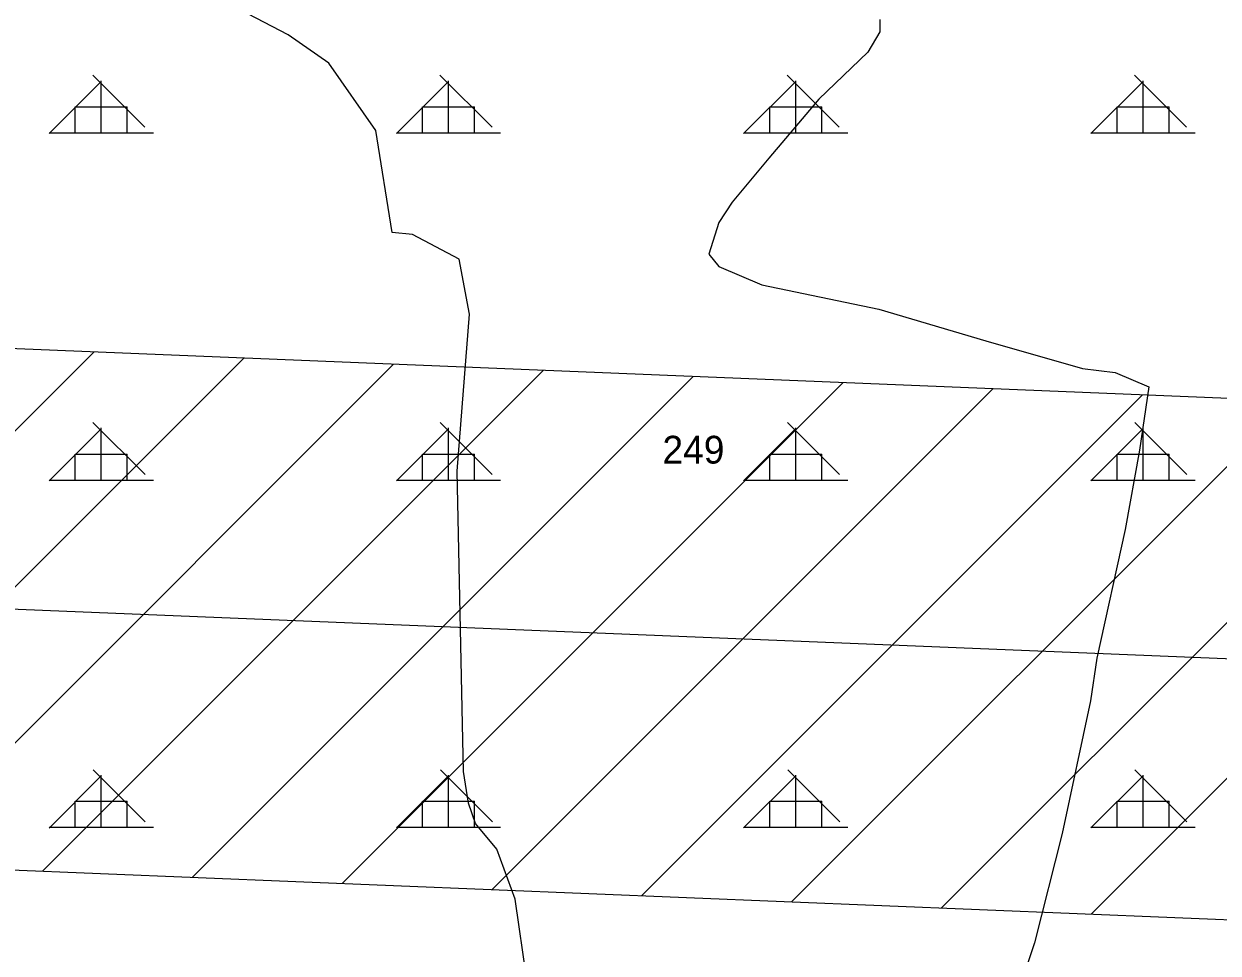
# Model space of a CAD drawing. Extents: x 410727 to 412947, y 4463506 to 4466382.
# Drawn here: x 411843.5 to 412015.4, y 4464905 to 4465038.8 of the extents above; entities that cross this region are included whole.
import ezdxf

# ---------------------------------------------------------------- set-up
doc = ezdxf.new("R2010")
doc.units = 0
for name, color, linetype in [('KDS_PARSEL_NO', 7, 'Continuous'), ('KDS_PL', 7, 'Continuous'), ('TA_ENH_HAT', 7, 'Continuous'), ('TA_ENH_TARAMA', 7, 'Continuous'), ('TR_ORMAN', 7, 'Continuous')]:
    doc.layers.add(name, color=color, linetype=linetype)

msp = doc.modelspace()

# ---------------------------------------------------------------- linework, layer by layer
at = {"layer": 'KDS_PL'}
for p, q in [((411881.55, 4465037.21), (411872.32, 4465042)), ((411966.73, 4465039.39), (411966.73, 4465037.63)), ((411887.41, 4465033.1), (411881.55, 4465037.21)), ((411966.73, 4465037.63), (411964.97, 4465034.69)), ((411964.97, 4465034.69), (411957.93, 4465027.94)), ((411894.16, 4465023.41), (411887.41, 4465033.1)), ((411957.93, 4465027.94), (411950.75, 4465019.42)), ((411896.5, 4465008.72), (411894.16, 4465023.41)), ((411950.75, 4465019.42), (411945.47, 4465013.1)), ((411945.47, 4465013.1), (411943.56, 4465010.16)), ((411899.43, 4465008.43), (411896.5, 4465008.72)), ((411943.56, 4465010.16), (411942.1, 4465005.61)), ((411906.17, 4465004.9), (411899.43, 4465008.43)), ((411942.1, 4465005.61), (411943.56, 4465003.85)), ((411907.64, 4464996.97), (411906.17, 4465004.9)), ((411943.56, 4465003.85), (411949.72, 4465001.2)), ((411949.72, 4465001.2), (411966.58, 4464997.68)), ((411905.88, 4464974.36), (411907.64, 4464996.97)), ((411966.58, 4464997.68), (411981.97, 4464993.13)), ((411981.97, 4464993.13), (411995.9, 4464989.16)), ((411995.9, 4464989.16), (412000.59, 4464988.57)), ((412000.59, 4464988.57), (412005.43, 4464986.52)), ((412005.43, 4464986.52), (412004.11, 4464977.41)), ((412004.11, 4464977.41), (412002.06, 4464965.95)), ((411906.76, 4464931.12), (411905.88, 4464974.36)), ((412002.06, 4464965.95), (411997.95, 4464947.45)), ((411997.95, 4464947.45), (411997.07, 4464941.28)), ((411997.07, 4464941.28), (411992.97, 4464922.18)), ((411907.49, 4464926.57), (411906.76, 4464931.12)), ((411908.52, 4464923.63), (411907.49, 4464926.57)), ((411911.59, 4464919.96), (411908.52, 4464923.63)), ((411992.97, 4464922.18), (411989.01, 4464906.46)), ((411914.23, 4464912.76), (411911.59, 4464919.96)), ((411916.14, 4464899.55), (411914.23, 4464912.76)), ((411989.01, 4464906.46), (411985.05, 4464894.86))]:
    msp.add_line(p, q, dxfattribs=at)
at = {"layer": 'TA_ENH_HAT'}
msp.add_lwpolyline([(412066.99, 4464945.27), (411603.01, 4464964.25), (411201.24, 4464983.22), (410781.64, 4465000.65)], dxfattribs=at)
at = {"layer": 'TA_ENH_TARAMA'}
for p, q in [((411781.47, 4464919.42), (411853.58, 4464991.53)), ((411781.47, 4464919.42), (411853.58, 4464991.53)), ((411803.03, 4464918.54), (411875.15, 4464990.65)), ((411803.03, 4464918.54), (411875.15, 4464990.65)), ((411824.6, 4464917.66), (411896.72, 4464989.77)), ((411824.6, 4464917.66), (411896.72, 4464989.77)), ((411846.17, 4464916.77), (411918.29, 4464988.89)), ((411846.17, 4464916.77), (411918.29, 4464988.89)), ((411867.74, 4464915.89), (411939.85, 4464988)), ((411867.74, 4464915.89), (411939.85, 4464988)), ((411889.31, 4464915.01), (411961.42, 4464987.12)), ((411889.31, 4464915.01), (411961.42, 4464987.12)), ((411910.88, 4464914.13), (411982.99, 4464986.24)), ((411910.88, 4464914.13), (411982.99, 4464986.24)), ((411932.45, 4464913.25), (412004.56, 4464985.36)), ((411932.45, 4464913.25), (412004.56, 4464985.36)), ((411954.02, 4464912.36), (412026.13, 4464984.48)), ((411954.02, 4464912.36), (412026.13, 4464984.48)), ((411975.58, 4464911.48), (412047.7, 4464983.59)), ((411975.58, 4464911.48), (412047.7, 4464983.59)), ((411997.15, 4464910.6), (412068.49, 4464981.94)), ((411997.15, 4464910.6), (412068.49, 4464981.94))]:
    msp.add_line(p, q, dxfattribs=at)
msp.add_lwpolyline([(410782.08, 4465038.16), (410781.19, 4464963.13), (411199.57, 4464945.75), (411601.36, 4464926.78), (412065.46, 4464907.81), (412068.53, 4464982.74), (411604.66, 4465001.71), (411202.9, 4465020.68), (410782.08, 4465038.16)], dxfattribs=at)
at = {"layer": 'TR_ORMAN'}
for p, q in [((411860.9, 4465023.92), (411853.4, 4465031.41)), ((411860.9, 4465023.92), (411853.4, 4465031.41)), ((411860.9, 4465023.92), (411853.4, 4465031.41)), ((411860.9, 4465023.92), (411853.4, 4465031.41)), ((411910.89, 4465023.92), (411903.39, 4465031.41)), ((411910.89, 4465023.92), (411903.39, 4465031.41)), ((411910.89, 4465023.92), (411903.39, 4465031.41)), ((411910.89, 4465023.92), (411903.39, 4465031.41)), ((411960.88, 4465023.92), (411953.38, 4465031.41)), ((411960.88, 4465023.92), (411953.38, 4465031.41)), ((411960.88, 4465023.92), (411953.38, 4465031.41)), ((411960.88, 4465023.92), (411953.38, 4465031.41)), ((412010.88, 4465023.92), (412003.38, 4465031.41)), ((412010.88, 4465023.92), (412003.38, 4465031.41)), ((412010.88, 4465023.92), (412003.38, 4465031.41)), ((412010.88, 4465023.92), (412003.38, 4465031.41)), ((411847.12, 4465022.97), (411854.61, 4465030.47)), ((411847.12, 4465022.97), (411854.61, 4465030.47)), ((411847.12, 4465022.97), (411854.61, 4465030.47)), ((411847.12, 4465022.97), (411854.61, 4465030.47)), ((411854.62, 4465023.09), (411854.62, 4465030.59)), ((411854.62, 4465023.09), (411854.62, 4465030.59)), ((411854.62, 4465023.09), (411854.62, 4465030.59)), ((411854.62, 4465023.09), (411854.62, 4465030.59)), ((411897.11, 4465022.97), (411904.61, 4465030.47)), ((411897.11, 4465022.97), (411904.61, 4465030.47)), ((411897.11, 4465022.97), (411904.61, 4465030.47)), ((411897.11, 4465022.97), (411904.61, 4465030.47)), ((411904.62, 4465023.09), (411904.62, 4465030.59)), ((411904.62, 4465023.09), (411904.62, 4465030.59)), ((411904.62, 4465023.09), (411904.62, 4465030.59)), ((411904.62, 4465023.09), (411904.62, 4465030.59)), ((411947.11, 4465022.98), (411954.61, 4465030.48)), ((411947.11, 4465022.98), (411954.61, 4465030.48)), ((411947.11, 4465022.98), (411954.61, 4465030.48)), ((411947.11, 4465022.98), (411954.61, 4465030.48)), ((411954.62, 4465023.09), (411954.62, 4465030.59)), ((411954.62, 4465023.09), (411954.62, 4465030.59)), ((411954.62, 4465023.09), (411954.62, 4465030.59)), ((411954.62, 4465023.09), (411954.62, 4465030.59)), ((411997.11, 4465022.99), (412004.61, 4465030.49)), ((411997.11, 4465022.99), (412004.61, 4465030.49)), ((411997.11, 4465022.99), (412004.61, 4465030.49)), ((411997.11, 4465022.99), (412004.61, 4465030.49)), ((412004.62, 4465023.09), (412004.62, 4465030.59)), ((412004.62, 4465023.09), (412004.62, 4465030.59)), ((412004.62, 4465023.09), (412004.62, 4465030.59)), ((412004.62, 4465023.09), (412004.62, 4465030.59)), ((411850.87, 4465023.09), (411850.87, 4465026.84)), ((411850.87, 4465026.84), (411858.37, 4465026.84)), ((411850.87, 4465023.09), (411850.87, 4465026.84)), ((411850.87, 4465026.84), (411858.37, 4465026.84)), ((411850.87, 4465023.09), (411850.87, 4465026.84)), ((411850.87, 4465026.84), (411858.37, 4465026.84)), ((411850.87, 4465023.09), (411850.87, 4465026.84)), ((411850.87, 4465026.84), (411858.37, 4465026.84)), ((411858.37, 4465023.09), (411858.37, 4465026.84)), ((411858.37, 4465023.09), (411858.37, 4465026.84)), ((411858.37, 4465023.09), (411858.37, 4465026.84)), ((411858.37, 4465023.09), (411858.37, 4465026.84)), ((411900.87, 4465023.09), (411900.87, 4465026.84)), ((411900.87, 4465026.84), (411908.37, 4465026.84)), ((411900.87, 4465023.09), (411900.87, 4465026.84)), ((411900.87, 4465026.84), (411908.37, 4465026.84)), ((411900.87, 4465023.09), (411900.87, 4465026.84)), ((411900.87, 4465026.84), (411908.37, 4465026.84)), ((411900.87, 4465023.09), (411900.87, 4465026.84)), ((411900.87, 4465026.84), (411908.37, 4465026.84)), ((411908.37, 4465023.09), (411908.37, 4465026.84)), ((411908.37, 4465023.09), (411908.37, 4465026.84)), ((411908.37, 4465023.09), (411908.37, 4465026.84)), ((411908.37, 4465023.09), (411908.37, 4465026.84)), ((411950.87, 4465023.09), (411950.87, 4465026.84)), ((411950.87, 4465026.84), (411958.37, 4465026.84)), ((411950.87, 4465023.09), (411950.87, 4465026.84)), ((411950.87, 4465026.84), (411958.37, 4465026.84)), ((411950.87, 4465023.09), (411950.87, 4465026.84)), ((411950.87, 4465026.84), (411958.37, 4465026.84)), ((411950.87, 4465023.09), (411950.87, 4465026.84)), ((411950.87, 4465026.84), (411958.37, 4465026.84)), ((411958.37, 4465023.09), (411958.37, 4465026.84)), ((411958.37, 4465023.09), (411958.37, 4465026.84)), ((411958.37, 4465023.09), (411958.37, 4465026.84)), ((411958.37, 4465023.09), (411958.37, 4465026.84)), ((412000.87, 4465023.09), (412000.87, 4465026.84)), ((412000.87, 4465026.84), (412008.37, 4465026.84)), ((412000.87, 4465023.09), (412000.87, 4465026.84)), ((412000.87, 4465026.84), (412008.37, 4465026.84)), ((412000.87, 4465023.09), (412000.87, 4465026.84)), ((412000.87, 4465026.84), (412008.37, 4465026.84)), ((412000.87, 4465023.09), (412000.87, 4465026.84)), ((412000.87, 4465026.84), (412008.37, 4465026.84)), ((412008.37, 4465023.09), (412008.37, 4465026.84)), ((412008.37, 4465023.09), (412008.37, 4465026.84)), ((412008.37, 4465023.09), (412008.37, 4465026.84)), ((412008.37, 4465023.09), (412008.37, 4465026.84)), ((411847.12, 4465023.09), (411862.12, 4465023.09)), ((411847.12, 4465023.09), (411862.12, 4465023.09)), ((411847.12, 4465023.09), (411862.12, 4465023.09)), ((411847.12, 4465023.09), (411862.12, 4465023.09)), ((411897.12, 4465023.09), (411912.12, 4465023.09)), ((411897.12, 4465023.09), (411912.12, 4465023.09)), ((411897.12, 4465023.09), (411912.12, 4465023.09)), ((411897.12, 4465023.09), (411912.12, 4465023.09)), ((411947.12, 4465023.09), (411962.12, 4465023.09)), ((411947.12, 4465023.09), (411962.12, 4465023.09)), ((411947.12, 4465023.09), (411962.12, 4465023.09)), ((411947.12, 4465023.09), (411962.12, 4465023.09)), ((411997.12, 4465023.09), (412012.12, 4465023.09)), ((411997.12, 4465023.09), (412012.12, 4465023.09)), ((411997.12, 4465023.09), (412012.12, 4465023.09)), ((411997.12, 4465023.09), (412012.12, 4465023.09)), ((411860.93, 4464973.89), (411853.43, 4464981.39)), ((411860.93, 4464973.89), (411853.43, 4464981.39)), ((411860.93, 4464973.89), (411853.43, 4464981.39)), ((411860.93, 4464973.89), (411853.43, 4464981.39)), ((411910.92, 4464973.89), (411903.42, 4464981.39)), ((411910.92, 4464973.89), (411903.42, 4464981.39)), ((411910.92, 4464973.89), (411903.42, 4464981.39)), ((411910.92, 4464973.89), (411903.42, 4464981.39)), ((411960.92, 4464973.89), (411953.42, 4464981.39)), ((411960.92, 4464973.89), (411953.42, 4464981.39)), ((411960.92, 4464973.89), (411953.42, 4464981.39)), ((411960.92, 4464973.89), (411953.42, 4464981.39)), ((412010.91, 4464973.89), (412003.41, 4464981.39)), ((412010.91, 4464973.89), (412003.41, 4464981.39)), ((412010.91, 4464973.89), (412003.41, 4464981.39)), ((412010.91, 4464973.89), (412003.41, 4464981.39)), ((411847.12, 4464972.98), (411854.61, 4464980.47)), ((411847.12, 4464972.98), (411854.61, 4464980.47)), ((411847.12, 4464972.98), (411854.61, 4464980.47)), ((411847.12, 4464972.98), (411854.61, 4464980.47)), ((411854.62, 4464973.09), (411854.62, 4464980.59)), ((411854.62, 4464973.09), (411854.62, 4464980.59)), ((411854.62, 4464973.09), (411854.62, 4464980.59)), ((411854.62, 4464973.09), (411854.62, 4464980.59)), ((411897.11, 4464972.98), (411904.61, 4464980.48)), ((411897.11, 4464972.98), (411904.61, 4464980.48)), ((411897.11, 4464972.98), (411904.61, 4464980.48)), ((411897.11, 4464972.98), (411904.61, 4464980.48)), ((411904.62, 4464973.09), (411904.62, 4464980.59)), ((411904.62, 4464973.09), (411904.62, 4464980.59)), ((411904.62, 4464973.09), (411904.62, 4464980.59)), ((411904.62, 4464973.09), (411904.62, 4464980.59)), ((411947.11, 4464972.99), (411954.61, 4464980.49)), ((411947.11, 4464972.99), (411954.61, 4464980.49)), ((411947.11, 4464972.99), (411954.61, 4464980.49)), ((411947.11, 4464972.99), (411954.61, 4464980.49)), ((411954.62, 4464973.09), (411954.62, 4464980.59)), ((411954.62, 4464973.09), (411954.62, 4464980.59)), ((411954.62, 4464973.09), (411954.62, 4464980.59)), ((411954.62, 4464973.09), (411954.62, 4464980.59)), ((411997.11, 4464973), (412004.61, 4464980.5)), ((411997.11, 4464973), (412004.61, 4464980.5)), ((411997.11, 4464973), (412004.61, 4464980.5)), ((411997.11, 4464973), (412004.61, 4464980.5)), ((412004.62, 4464973.09), (412004.62, 4464980.59)), ((412004.62, 4464973.09), (412004.62, 4464980.59)), ((412004.62, 4464973.09), (412004.62, 4464980.59)), ((412004.62, 4464973.09), (412004.62, 4464980.59)), ((411850.87, 4464973.09), (411850.87, 4464976.84)), ((411850.87, 4464976.84), (411858.37, 4464976.84)), ((411850.87, 4464973.09), (411850.87, 4464976.84)), ((411850.87, 4464976.84), (411858.37, 4464976.84)), ((411850.87, 4464973.09), (411850.87, 4464976.84)), ((411850.87, 4464976.84), (411858.37, 4464976.84)), ((411850.87, 4464973.09), (411850.87, 4464976.84)), ((411850.87, 4464976.84), (411858.37, 4464976.84)), ((411858.37, 4464973.09), (411858.37, 4464976.84)), ((411858.37, 4464973.09), (411858.37, 4464976.84)), ((411858.37, 4464973.09), (411858.37, 4464976.84)), ((411858.37, 4464973.09), (411858.37, 4464976.84)), ((411900.87, 4464973.09), (411900.87, 4464976.84)), ((411900.87, 4464976.84), (411908.37, 4464976.84)), ((411900.87, 4464973.09), (411900.87, 4464976.84)), ((411900.87, 4464976.84), (411908.37, 4464976.84)), ((411900.87, 4464973.09), (411900.87, 4464976.84)), ((411900.87, 4464976.84), (411908.37, 4464976.84)), ((411900.87, 4464973.09), (411900.87, 4464976.84)), ((411900.87, 4464976.84), (411908.37, 4464976.84)), ((411908.37, 4464973.09), (411908.37, 4464976.84)), ((411908.37, 4464973.09), (411908.37, 4464976.84)), ((411908.37, 4464973.09), (411908.37, 4464976.84)), ((411908.37, 4464973.09), (411908.37, 4464976.84)), ((411950.87, 4464973.09), (411950.87, 4464976.84)), ((411950.87, 4464976.84), (411958.37, 4464976.84)), ((411950.87, 4464973.09), (411950.87, 4464976.84)), ((411950.87, 4464976.84), (411958.37, 4464976.84)), ((411950.87, 4464973.09), (411950.87, 4464976.84)), ((411950.87, 4464976.84), (411958.37, 4464976.84)), ((411950.87, 4464973.09), (411950.87, 4464976.84)), ((411950.87, 4464976.84), (411958.37, 4464976.84)), ((411958.37, 4464973.09), (411958.37, 4464976.84)), ((411958.37, 4464973.09), (411958.37, 4464976.84)), ((411958.37, 4464973.09), (411958.37, 4464976.84)), ((411958.37, 4464973.09), (411958.37, 4464976.84)), ((412000.87, 4464973.09), (412000.87, 4464976.84)), ((412000.87, 4464976.84), (412008.37, 4464976.84)), ((412000.87, 4464973.09), (412000.87, 4464976.84)), ((412000.87, 4464976.84), (412008.37, 4464976.84)), ((412000.87, 4464973.09), (412000.87, 4464976.84)), ((412000.87, 4464976.84), (412008.37, 4464976.84)), ((412000.87, 4464973.09), (412000.87, 4464976.84)), ((412000.87, 4464976.84), (412008.37, 4464976.84)), ((412008.37, 4464973.09), (412008.37, 4464976.84)), ((412008.37, 4464973.09), (412008.37, 4464976.84)), ((412008.37, 4464973.09), (412008.37, 4464976.84)), ((412008.37, 4464973.09), (412008.37, 4464976.84)), ((411847.12, 4464973.09), (411862.12, 4464973.09)), ((411847.12, 4464973.09), (411862.12, 4464973.09)), ((411847.12, 4464973.09), (411862.12, 4464973.09)), ((411847.12, 4464973.09), (411862.12, 4464973.09)), ((411897.12, 4464973.09), (411912.12, 4464973.09)), ((411897.12, 4464973.09), (411912.12, 4464973.09)), ((411897.12, 4464973.09), (411912.12, 4464973.09)), ((411897.12, 4464973.09), (411912.12, 4464973.09)), ((411947.12, 4464973.09), (411962.12, 4464973.09)), ((411947.12, 4464973.09), (411962.12, 4464973.09)), ((411947.12, 4464973.09), (411962.12, 4464973.09)), ((411947.12, 4464973.09), (411962.12, 4464973.09)), ((411997.12, 4464973.09), (412012.12, 4464973.09)), ((411997.12, 4464973.09), (412012.12, 4464973.09)), ((411997.12, 4464973.09), (412012.12, 4464973.09)), ((411997.12, 4464973.09), (412012.12, 4464973.09)), ((411860.96, 4464923.87), (411853.46, 4464931.37)), ((411860.96, 4464923.87), (411853.46, 4464931.37)), ((411860.96, 4464923.87), (411853.46, 4464931.37)), ((411860.96, 4464923.87), (411853.46, 4464931.37)), ((411910.95, 4464923.87), (411903.46, 4464931.37)), ((411910.95, 4464923.87), (411903.46, 4464931.37)), ((411910.95, 4464923.87), (411903.46, 4464931.37)), ((411910.95, 4464923.87), (411903.46, 4464931.37)), ((411960.95, 4464923.87), (411953.45, 4464931.37)), ((411960.95, 4464923.87), (411953.45, 4464931.37)), ((411960.95, 4464923.87), (411953.45, 4464931.37)), ((411960.95, 4464923.87), (411953.45, 4464931.37)), ((412010.94, 4464923.87), (412003.44, 4464931.37)), ((412010.94, 4464923.87), (412003.44, 4464931.37)), ((412010.94, 4464923.87), (412003.44, 4464931.37)), ((412010.94, 4464923.87), (412003.44, 4464931.37)), ((411847.12, 4464922.98), (411854.61, 4464930.48)), ((411847.12, 4464922.98), (411854.61, 4464930.48)), ((411847.12, 4464922.98), (411854.61, 4464930.48)), ((411847.12, 4464922.98), (411854.61, 4464930.48)), ((411854.62, 4464923.09), (411854.62, 4464930.59)), ((411854.62, 4464923.09), (411854.62, 4464930.59)), ((411854.62, 4464923.09), (411854.62, 4464930.59)), ((411854.62, 4464923.09), (411854.62, 4464930.59)), ((411897.11, 4464922.99), (411904.61, 4464930.49)), ((411897.11, 4464922.99), (411904.61, 4464930.49)), ((411897.11, 4464922.99), (411904.61, 4464930.49)), ((411897.11, 4464922.99), (411904.61, 4464930.49)), ((411904.62, 4464923.09), (411904.62, 4464930.59)), ((411904.62, 4464923.09), (411904.62, 4464930.59)), ((411904.62, 4464923.09), (411904.62, 4464930.59)), ((411904.62, 4464923.09), (411904.62, 4464930.59)), ((411947.11, 4464923), (411954.61, 4464930.5)), ((411947.11, 4464923), (411954.61, 4464930.5)), ((411947.11, 4464923), (411954.61, 4464930.5)), ((411947.11, 4464923), (411954.61, 4464930.5)), ((411954.62, 4464923.09), (411954.62, 4464930.59)), ((411954.62, 4464923.09), (411954.62, 4464930.59)), ((411954.62, 4464923.09), (411954.62, 4464930.59)), ((411954.62, 4464923.09), (411954.62, 4464930.59)), ((411997.11, 4464923), (412004.61, 4464930.5)), ((411997.11, 4464923), (412004.61, 4464930.5)), ((411997.11, 4464923), (412004.61, 4464930.5)), ((411997.11, 4464923), (412004.61, 4464930.5)), ((412004.62, 4464923.09), (412004.62, 4464930.59)), ((412004.62, 4464923.09), (412004.62, 4464930.59)), ((412004.62, 4464923.09), (412004.62, 4464930.59)), ((412004.62, 4464923.09), (412004.62, 4464930.59)), ((411850.87, 4464923.09), (411850.87, 4464926.84)), ((411850.87, 4464926.84), (411858.37, 4464926.84)), ((411850.87, 4464923.09), (411850.87, 4464926.84)), ((411850.87, 4464926.84), (411858.37, 4464926.84)), ((411850.87, 4464923.09), (411850.87, 4464926.84)), ((411850.87, 4464926.84), (411858.37, 4464926.84)), ((411850.87, 4464923.09), (411850.87, 4464926.84)), ((411850.87, 4464926.84), (411858.37, 4464926.84)), ((411858.37, 4464923.09), (411858.37, 4464926.84)), ((411858.37, 4464923.09), (411858.37, 4464926.84)), ((411858.37, 4464923.09), (411858.37, 4464926.84)), ((411858.37, 4464923.09), (411858.37, 4464926.84)), ((411900.87, 4464923.09), (411900.87, 4464926.84)), ((411900.87, 4464926.84), (411908.37, 4464926.84)), ((411900.87, 4464923.09), (411900.87, 4464926.84)), ((411900.87, 4464926.84), (411908.37, 4464926.84)), ((411900.87, 4464923.09), (411900.87, 4464926.84)), ((411900.87, 4464926.84), (411908.37, 4464926.84)), ((411900.87, 4464923.09), (411900.87, 4464926.84)), ((411900.87, 4464926.84), (411908.37, 4464926.84)), ((411908.37, 4464923.09), (411908.37, 4464926.84)), ((411908.37, 4464923.09), (411908.37, 4464926.84)), ((411908.37, 4464923.09), (411908.37, 4464926.84)), ((411908.37, 4464923.09), (411908.37, 4464926.84)), ((411950.87, 4464923.09), (411950.87, 4464926.84)), ((411950.87, 4464926.84), (411958.37, 4464926.84)), ((411950.87, 4464923.09), (411950.87, 4464926.84)), ((411950.87, 4464926.84), (411958.37, 4464926.84)), ((411950.87, 4464923.09), (411950.87, 4464926.84)), ((411950.87, 4464926.84), (411958.37, 4464926.84)), ((411950.87, 4464923.09), (411950.87, 4464926.84)), ((411950.87, 4464926.84), (411958.37, 4464926.84)), ((411958.37, 4464923.09), (411958.37, 4464926.84)), ((411958.37, 4464923.09), (411958.37, 4464926.84)), ((411958.37, 4464923.09), (411958.37, 4464926.84)), ((411958.37, 4464923.09), (411958.37, 4464926.84)), ((412000.87, 4464923.09), (412000.87, 4464926.84)), ((412000.87, 4464926.84), (412008.37, 4464926.84)), ((412000.87, 4464923.09), (412000.87, 4464926.84)), ((412000.87, 4464926.84), (412008.37, 4464926.84)), ((412000.87, 4464923.09), (412000.87, 4464926.84)), ((412000.87, 4464926.84), (412008.37, 4464926.84)), ((412000.87, 4464923.09), (412000.87, 4464926.84)), ((412000.87, 4464926.84), (412008.37, 4464926.84)), ((412008.37, 4464923.09), (412008.37, 4464926.84)), ((412008.37, 4464923.09), (412008.37, 4464926.84)), ((412008.37, 4464923.09), (412008.37, 4464926.84)), ((412008.37, 4464923.09), (412008.37, 4464926.84)), ((411847.12, 4464923.09), (411862.12, 4464923.09)), ((411847.12, 4464923.09), (411862.12, 4464923.09)), ((411847.12, 4464923.09), (411862.12, 4464923.09)), ((411847.12, 4464923.09), (411862.12, 4464923.09)), ((411897.12, 4464923.09), (411912.12, 4464923.09)), ((411897.12, 4464923.09), (411912.12, 4464923.09)), ((411897.12, 4464923.09), (411912.12, 4464923.09)), ((411897.12, 4464923.09), (411912.12, 4464923.09)), ((411947.12, 4464923.09), (411962.12, 4464923.09)), ((411947.12, 4464923.09), (411962.12, 4464923.09)), ((411947.12, 4464923.09), (411962.12, 4464923.09)), ((411947.12, 4464923.09), (411962.12, 4464923.09)), ((411997.12, 4464923.09), (412012.12, 4464923.09)), ((411997.12, 4464923.09), (412012.12, 4464923.09)), ((411997.12, 4464923.09), (412012.12, 4464923.09)), ((411997.12, 4464923.09), (412012.12, 4464923.09))]:
    msp.add_line(p, q, dxfattribs=at)

# ---------------------------------------------------------------- texts
at = {"layer": 'KDS_PARSEL_NO'}
msp.add_text('249', height=4, dxfattribs=at).set_placement((411935.42, 4464975.46))

doc.saveas('drawing.dxf')
